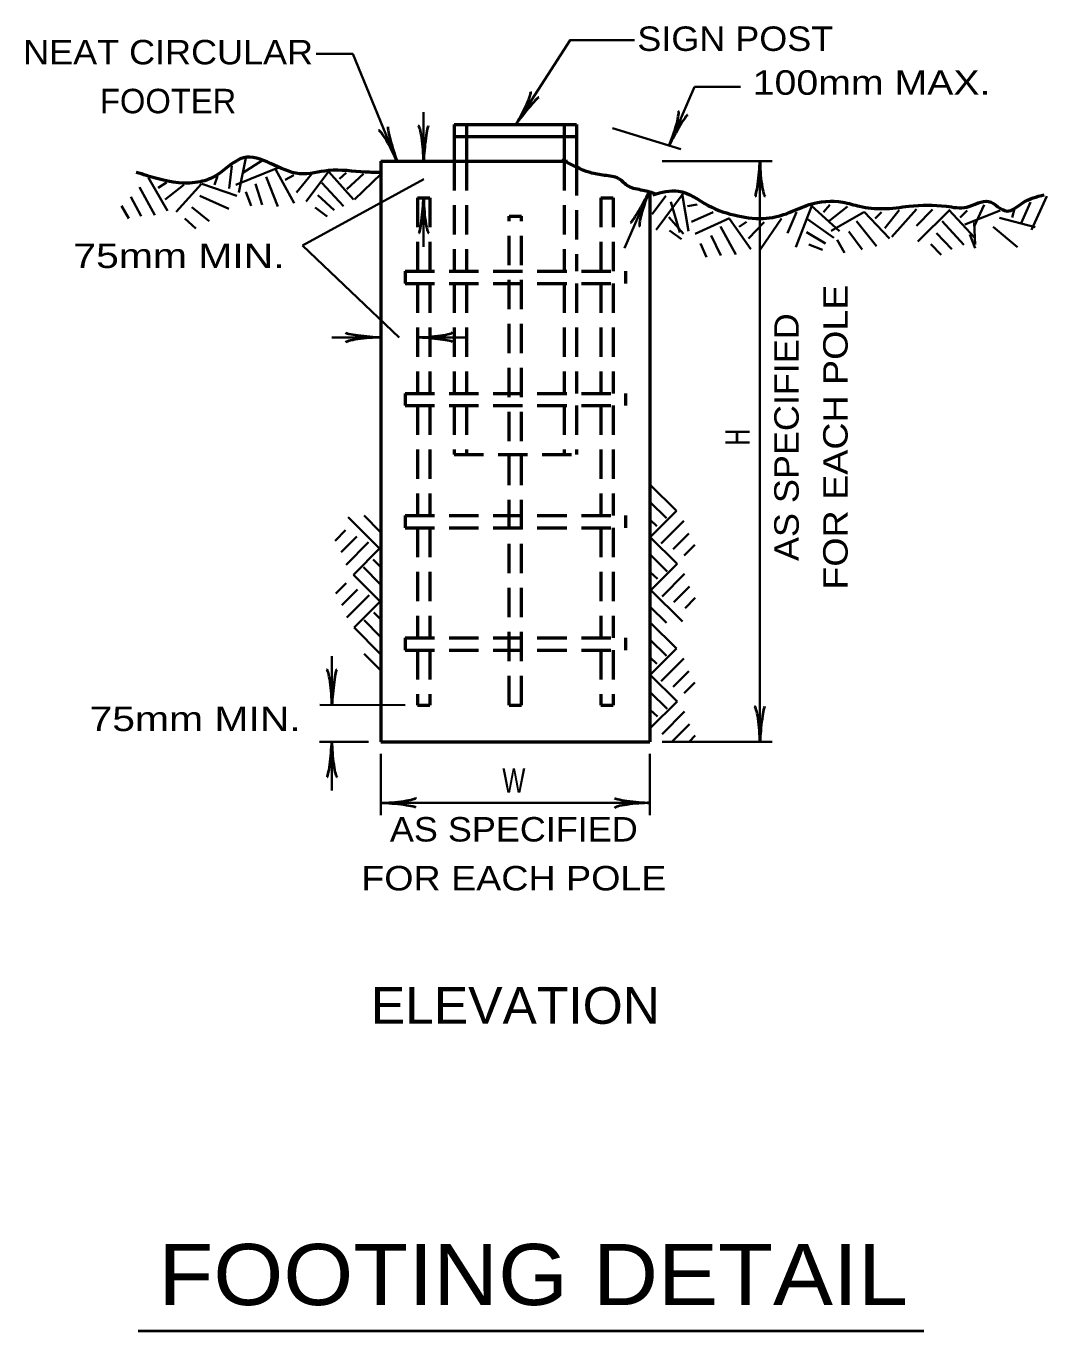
# Model space of a CAD drawing. Extents: x -27 to 828, y -12 to 532.
# Drawn here: x 442.8 to 542.9, y 166.3 to 294.4 of the extents above; entities that cross this region are included whole.
import ezdxf
from ezdxf.enums import TextEntityAlignment as Align

# ---------------------------------------------------------------- set-up
doc = ezdxf.new("R2010")
doc.units = 0
doc.header["$LTSCALE"] = 0.96
doc.linetypes.add('MEDIUM_DASHED', pattern=[4.5, 3, -1.5])
doc.layers.add('1', color=7, linetype='Continuous', lineweight=35)

msp = doc.modelspace()

# ---------------------------------------------------------------- linework, layer by layer
at = {"layer": '1'}
for p, q in [((505.8728, 282.6366), (508.3642, 288.3828)), ((508.3642, 288.3828), (512.887, 288.3828)), ((481.7762, 281.1069), (481.7762, 285.9069)), ((500.3226, 284.3524), (507.0331, 282.2778)), ((462.9633, 280.631), (462.6927, 278.4073)), ((464.373, 281.5802), (463.6367, 278.024)), ((465.9436, 281.1514), (464.0411, 279.9687)), ((505.1762, 281.1069), (515.9762, 281.1069)), ((514.7762, 281.1069), (514.7762, 224.1069)), ((454.778, 279.4722), (456.6378, 276.2349)), ((461.5546, 279.6169), (461.2696, 278.7817)), ((467.4886, 280.4349), (463.3678, 278.7651)), ((466.3373, 279.5709), (467.474, 276.6443)), ((467.2913, 280.2549), (469.0651, 276.9697)), ((469.039, 279.7328), (468.1959, 279.2583)), ((470.7845, 279.828), (469.2964, 278.0196)), ((481.8107, 279.3192), (469.8875, 272.8224)), ((472.4682, 280.1103), (470.2438, 277.1329)), ((472.4657, 280.0413), (474.8968, 277.3433)), ((474.1675, 279.9531), (473.5125, 279.3617)), ((475.8933, 279.8651), (474.2307, 278.3638)), ((477.5996, 279.8586), (475.0005, 277.3221)), ((453.9006, 278.5569), (455.4045, 275.801)), ((456.5465, 279.0168), (455.7448, 278.4752)), ((458.2618, 278.7806), (456.4249, 277.3279)), ((459.9754, 278.8812), (457.4907, 276.1173)), ((460.0252, 278.8655), (463.4624, 277.693)), ((464.344, 278.0826), (464.8505, 276.7319)), ((465.2849, 278.8684), (465.9522, 276.8012)), ((471.7986, 278.9801), (473.9151, 276.6842)), ((501.5022, 272.5563), (503.889, 278.0612)), ((452.1493, 276.7267), (452.8483, 275.4648)), ((453.041, 277.6119), (454.0712, 275.6996)), ((459.8051, 277.6916), (462.6641, 276.4359)), ((471.3892, 277.7657), (472.9887, 276.296)), ((481.7762, 272.7069), (481.7762, 277.5069)), ((505.5501, 277.6915), (504.2154, 275.8925)), ((507.2357, 277.9413), (504.5864, 274.3705)), ((506.0429, 277.1085), (506.9159, 274.0927)), ((507.1495, 277.9097), (507.7565, 274.2258)), ((508.6318, 276.8467), (507.6801, 276.6727)), ((519.9205, 276.8087), (518.3152, 272.6623)), ((519.8294, 276.7304), (522.5968, 274.2243)), ((521.6512, 276.8206), (521.0145, 276.0922)), ((536.7836, 276.8257), (535.7945, 274.7029)), ((541.3435, 277.0668), (540.4192, 275.0262)), ((542.9382, 277.6672), (541.4397, 274.359)), ((458.3395, 275.4617), (459.4204, 274.4811)), ((459.0429, 276.5873), (460.734, 275.2239)), ((471.1485, 276.5568), (472.3137, 275.678)), ((505.8362, 275.5933), (507.2687, 273.9604)), ((510.1984, 276.1041), (508.0549, 275.1608)), ((511.7941, 275.5048), (508.416, 273.9552)), ((511.7944, 275.443), (513.8853, 272.4736)), ((516.8906, 275.4733), (514.8385, 272.477)), ((518.3683, 276.1003), (517.4853, 274.0415)), ((519.4613, 275.4065), (522.0201, 273.5872)), ((523.3626, 276.6413), (521.5219, 275.1934)), ((524.9828, 276.1067), (521.7556, 274.2633)), ((525.0146, 276.1408), (527.5079, 273.5002)), ((526.7192, 276.1009), (526.0934, 275.4787)), ((528.4434, 276.2832), (527.0496, 274.5294)), ((530.1401, 276.4017), (527.7286, 273.6861)), ((531.7232, 276.3471), (530.1397, 274.7626)), ((533.4268, 276.3327), (530.2606, 273.2111)), ((533.3048, 276.3085), (535.8558, 273.5824)), ((535.1278, 276.248), (534.4331, 275.5747)), ((538.3478, 276.2539), (534.8975, 274.8724)), ((538.2868, 275.5487), (541.8019, 274.6359)), ((539.7545, 276.4153), (539.5407, 275.5591)), ((505.9071, 274.2992), (507.0757, 273.4533)), ((510.9113, 274.6717), (512.4221, 271.9389)), ((513.4732, 275.1515), (512.7517, 274.6435)), ((515.2091, 275.1177), (513.6486, 273.5106)), ((519.3394, 274.1185), (521.2135, 273.0201)), ((523.5134, 274.1946), (524.7988, 272.4435)), ((524.2695, 275.2198), (526.204, 272.7686)), ((532.6758, 275.1993), (534.8027, 272.8899)), ((535.7872, 275.0956), (535.9042, 272.9265)), ((537.6555, 274.6643), (540.0602, 272.6724)), ((508.9346, 273.0164), (509.5371, 271.6871)), ((509.9831, 273.7951), (510.9511, 271.8505)), ((519.5657, 272.9315), (520.9106, 272.4096)), ((522.3555, 273.3743), (523.0736, 272.1037)), ((531.5547, 272.9379), (532.5795, 271.9226)), ((532.1211, 274.0486), (533.6186, 272.475)), ((535.3694, 273.9092), (535.9057, 272.5519)), ((479.3873, 263.8044), (469.8875, 272.8224)), ((472.7762, 263.8044), (477.5762, 263.8044)), ((481.1762, 263.8044), (485.9762, 263.8044)), ((504.0242, 249.3309), (506.5922, 246.7629)), ((504.0242, 247.6269), (505.6082, 246.0429)), ((477.5282, 243.0189), (474.3842, 246.1629)), ((477.5282, 244.7229), (475.9442, 246.3069)), ((504.0242, 244.1949), (506.5922, 246.7629)), ((474.1202, 244.8669), (473.1122, 243.8349)), ((504.0242, 245.8989), (504.6482, 245.2749)), ((505.1042, 243.5709), (507.3122, 245.7789)), ((475.2242, 244.2669), (473.6882, 242.7309)), ((476.3762, 243.7149), (474.1682, 241.4829)), ((504.0242, 244.1949), (506.6642, 241.5789)), ((506.2562, 243.0189), (507.7922, 244.5549)), ((507.3602, 242.3949), (508.3922, 243.4269)), ((477.5282, 243.1389), (474.8882, 240.4989)), ((504.0242, 242.4909), (505.6802, 240.8349)), ((477.5282, 239.5869), (475.8722, 241.2429)), ((477.5282, 241.3149), (476.8322, 241.9869)), ((504.0242, 238.9389), (506.6642, 241.5789)), ((474.1922, 239.6829), (473.1602, 238.6509)), ((477.5282, 237.8829), (474.8882, 240.4989)), ((504.0242, 240.7629), (504.7202, 240.0909)), ((505.1762, 238.3629), (507.3842, 240.5949)), ((475.2962, 239.0589), (473.7602, 237.5229)), ((476.4482, 238.5069), (474.2402, 236.2989)), ((504.0242, 239.0589), (507.1682, 235.9149)), ((506.3282, 237.8109), (507.8642, 239.3469)), ((477.5282, 237.8829), (474.9602, 235.3149)), ((504.0242, 237.3549), (505.6082, 235.7709)), ((507.4322, 237.2109), (508.4402, 238.2429)), ((477.5282, 234.4509), (475.9442, 236.0349)), ((477.5282, 236.1789), (476.9042, 236.8029)), ((504.0242, 235.8189), (506.5922, 233.2509)), ((477.5282, 232.7469), (474.9602, 235.3149)), ((504.0242, 234.1149), (505.6082, 232.5309)), ((504.0242, 230.6829), (506.5922, 233.2509)), ((472.7826, 227.7239), (472.7826, 232.5239)), ((477.5282, 231.1629), (475.9442, 232.7469)), ((504.0242, 232.3869), (504.6482, 231.7629)), ((505.1042, 230.0589), (507.3122, 232.2669)), ((504.0242, 230.6829), (506.6642, 228.0669)), ((506.2562, 229.5069), (507.7922, 231.0429)), ((507.3602, 228.8829), (508.3922, 229.9149)), ((504.0242, 228.9789), (505.6802, 227.3229)), ((504.0242, 225.4269), (506.6642, 228.0669)), ((479.9762, 227.709), (471.5826, 227.7239)), ((504.0242, 227.2509), (504.7202, 226.5789)), ((505.1762, 224.8509), (507.3842, 227.0829)), ((506.1362, 224.1069), (507.8642, 225.8349)), ((507.8307, 224.1069), (508.4402, 224.7309)), ((476.3762, 224.1069), (471.5762, 224.1069)), ((472.7762, 224.1069), (472.7762, 219.3069)), ((477.5762, 222.9069), (477.5762, 216.9069)), ((503.9762, 222.9069), (503.9762, 216.9069)), ((505.1762, 224.1069), (515.9762, 224.1069)), ((477.5762, 218.1069), (503.9762, 218.1069))]:
    msp.add_line(p, q, dxfattribs=at)
at = {"layer": '1', "lineweight": 53}
for p, q in [((484.7762, 284.7069), (496.7762, 284.7069)), ((484.7762, 284.7069), (484.7762, 281.1069)), ((485.9762, 284.7069), (485.9762, 281.1069)), ((495.5762, 284.7069), (495.5762, 281.1069)), ((496.7762, 284.7069), (496.7762, 280.6022)), ((484.7762, 283.5069), (496.7762, 283.5069)), ((477.5762, 281.1069), (495.9091, 281.1069)), ((477.5762, 281.1069), (477.5762, 224.1069)), ((503.9762, 278.0362), (503.9762, 224.1069)), ((477.5762, 224.1069), (503.9762, 224.1069))]:
    msp.add_line(p, q, dxfattribs=at)
at = {"layer": '1', "linetype": 'MEDIUM_DASHED', "lineweight": 53}
for p, q in [((484.7762, 281.1069), (484.7762, 270.3069)), ((485.9762, 281.1069), (485.9762, 270.3069)), ((495.5762, 281.1069), (495.5762, 270.3069)), ((496.7762, 280.6022), (496.7762, 270.3069)), ((481.1762, 277.5069), (482.3762, 277.5069)), ((481.1762, 277.5069), (481.1762, 270.3069)), ((482.3762, 277.5069), (482.3762, 270.3069)), ((499.1762, 277.5069), (500.3762, 277.5069)), ((499.1762, 277.5069), (499.1762, 270.3069)), ((500.3762, 277.5069), (500.3762, 270.3069)), ((490.1762, 227.7069), (490.1762, 275.7069)), ((490.1762, 275.7069), (491.3762, 275.7069)), ((491.3762, 227.7069), (491.3762, 275.7069)), ((479.9762, 270.3069), (501.5762, 270.3069)), ((479.9762, 270.3069), (479.9762, 269.1069)), ((501.5762, 270.3069), (501.5762, 269.1069)), ((479.9762, 269.1069), (501.5762, 269.1069)), ((481.1762, 269.1069), (481.1762, 258.3069)), ((482.3762, 269.1069), (482.3762, 258.3069)), ((484.7762, 269.1069), (484.7762, 258.3069)), ((485.9762, 269.1069), (485.9762, 258.3069)), ((495.5762, 269.1069), (495.5762, 258.3069)), ((496.7762, 269.1069), (496.7762, 258.3069)), ((499.1762, 269.1069), (499.1762, 258.3069)), ((500.3762, 269.1069), (500.3762, 258.3069)), ((479.9762, 258.3069), (501.5762, 258.3069)), ((479.9762, 258.3069), (479.9762, 257.1069)), ((501.5762, 258.3069), (501.5762, 257.1069)), ((479.9762, 257.1069), (501.5762, 257.1069)), ((481.1762, 257.1069), (481.1762, 246.3069)), ((482.3762, 257.1069), (482.3762, 246.3069)), ((484.7762, 257.1069), (484.7762, 252.3069)), ((485.9762, 257.1069), (485.9762, 252.3069)), ((495.5762, 257.1069), (495.5762, 252.3069)), ((496.7762, 257.1069), (496.7762, 252.3069)), ((499.1762, 257.1069), (499.1762, 246.3069)), ((500.3762, 257.1069), (500.3762, 246.3069)), ((484.7762, 252.3069), (496.7762, 252.3069)), ((479.9762, 246.3069), (501.5762, 246.3069)), ((479.9762, 246.3069), (479.9762, 245.1069)), ((501.5762, 246.3069), (501.5762, 245.1069)), ((479.9762, 245.1069), (501.5762, 245.1069)), ((481.1762, 245.1069), (481.1762, 234.3069)), ((482.3762, 245.1069), (482.3762, 234.3069)), ((499.1762, 245.1069), (499.1762, 234.3069)), ((500.3762, 245.1069), (500.3762, 234.3069)), ((479.9762, 234.3069), (501.5762, 234.3069)), ((479.9762, 234.3069), (479.9762, 233.1069)), ((501.5762, 234.3069), (501.5762, 233.1069)), ((479.9762, 233.1069), (501.5762, 233.1069)), ((481.1762, 233.1069), (481.1762, 227.7069)), ((482.3762, 233.1069), (482.3762, 227.7069)), ((499.1762, 233.1069), (499.1762, 227.7069)), ((500.3762, 233.1069), (500.3762, 227.7069)), ((481.1762, 227.7069), (482.3762, 227.7069)), ((490.1762, 227.7069), (491.3762, 227.7069)), ((499.1762, 227.7069), (500.3762, 227.7069))]:
    msp.add_line(p, q, dxfattribs=at)
at = {"layer": '1', "lineweight": 40}
msp.add_line((453.784, 166.2729), (530.8554, 166.2729), dxfattribs=at)
at = {"layer": '1'}
for points in [[(490.8331, 284.7069), (496.1572, 292.9917), (502.4581, 292.9917)], [(479.1588, 281.1069), (474.8313, 291.6341), (471.2394, 291.6341)]]:
    msp.add_lwpolyline(points, dxfattribs=at)
at = {"layer": '1', "lineweight": 40}
for centre, major_axis, ratio, start_param, end_param in [((491.2621, 285.9877), (-1.0008, -1.904), 0.122415, 0.89635335, 3.14159265), ((491.2621, 285.9877), (-1.0008, -1.904), 0.122415, 0.89635335, 3.14159265), ((491.7736, 285.7008), (1.3168, 1.6592), 0.07063, 6.28230741, 8.55970261), ((491.7736, 285.7008), (1.3168, 1.6592), 0.07063, 6.28230741, 8.55970261), ((506.0895, 283.9699), (-0.6805, -2.0405), 0.122415, 0.89635335, 3.14159265), ((506.0895, 283.9699), (-0.6805, -2.0405), 0.122415, 0.89635335, 3.14159265), ((506.6406, 283.7692), (-1.0318, -1.85), 0.07063, 3.14071475, 5.41810995), ((506.6406, 283.7692), (-1.0318, -1.85), 0.07063, 3.14071475, 5.41810995), ((478.8824, 282.4471), (-0.6064, 2.0296), 0.07063, 6.28230741, 8.55970261), ((478.8824, 282.4471), (-0.6064, 2.0296), 0.07063, 6.28230741, 8.55970261), ((481.4446, 282.4163), (0.1874, -2.1428), 0.122415, 0.89635335, 3.14159265), ((481.4446, 282.4163), (0.1874, -2.1428), 0.122415, 0.89635335, 3.14159265), ((482.0301, 282.4515), (-0.2108, -2.1077), 0.07063, 3.14071475, 5.41810995), ((482.0301, 282.4515), (-0.2108, -2.1077), 0.07063, 3.14071475, 5.41810995), ((478.3543, 282.1919), (0.988, -1.9107), 0.122415, 0.89635335, 3.14159265), ((478.3543, 282.1919), (0.988, -1.9107), 0.122415, 0.89635335, 3.14159265), ((514.5223, 279.7623), (0.2108, 2.1077), 0.07063, 3.14071475, 5.41810995), ((514.5223, 279.7623), (0.2108, 2.1077), 0.07063, 3.14071475, 5.41810995), ((515.1078, 279.7975), (-0.1874, 2.1428), 0.122415, 0.89635335, 3.14159265), ((515.1078, 279.7975), (-0.1874, 2.1428), 0.122415, 0.89635335, 3.14159265), ((503.1212, 276.9286), (1.0318, 1.8499), 0.07063, 3.14071475, 5.41810995), ((503.6723, 276.7279), (0.6805, 2.0405), 0.122415, 0.89635335, 3.14159265), ((481.5223, 276.1623), (0.2108, 2.1077), 0.07063, 3.14071475, 5.41810995), ((481.5223, 276.1623), (0.2108, 2.1077), 0.07063, 3.14071475, 5.41810995), ((482.1078, 276.1975), (-0.1874, 2.1428), 0.122415, 0.89635335, 3.14159265), ((482.1078, 276.1975), (-0.1874, 2.1428), 0.122415, 0.89635335, 3.14159265), ((476.2316, 264.0583), (2.1077, -0.2108), 0.07063, 3.14071475, 5.41810995), ((476.2316, 264.0583), (2.1077, -0.2108), 0.07063, 3.14071475, 5.41810995), ((482.4856, 264.136), (-2.1428, -0.1874), 0.122415, 0.89635335, 3.14159265), ((476.2668, 263.4728), (2.1428, 0.1874), 0.122415, 0.89635335, 3.14159265), ((476.2668, 263.4728), (2.1428, 0.1874), 0.122415, 0.89635335, 3.14159265), ((482.5208, 263.5505), (-2.1077, 0.2108), 0.07063, 3.14071475, 5.41810995), ((472.451, 229.0333), (0.1874, -2.1428), 0.122415, 0.89635335, 3.14159265), ((472.451, 229.0333), (0.1874, -2.1428), 0.122415, 0.89635335, 3.14159265), ((473.0365, 229.0685), (-0.2108, -2.1077), 0.07063, 3.14071475, 5.41810995), ((473.0365, 229.0685), (-0.2108, -2.1077), 0.07063, 3.14071475, 5.41810995), ((514.4446, 225.4163), (0.1874, -2.1428), 0.122415, 0.89635335, 3.14159265), ((514.4446, 225.4163), (0.1874, -2.1428), 0.122415, 0.89635335, 3.14159265), ((515.0301, 225.4515), (-0.2108, -2.1077), 0.07063, 3.14071475, 5.41810995), ((515.0301, 225.4515), (-0.2108, -2.1077), 0.07063, 3.14071475, 5.41810995), ((472.5223, 222.7623), (0.2108, 2.1077), 0.07063, 3.14071475, 5.41810995), ((472.5223, 222.7623), (0.2108, 2.1077), 0.07063, 3.14071475, 5.41810995), ((473.1078, 222.7975), (-0.1874, 2.1428), 0.122415, 0.89635335, 3.14159265), ((473.1078, 222.7975), (-0.1874, 2.1428), 0.122415, 0.89635335, 3.14159265), ((478.9208, 217.853), (-2.1077, 0.2108), 0.07063, 3.14071475, 5.41810995), ((478.9208, 217.853), (-2.1077, 0.2108), 0.07063, 3.14071475, 5.41810995), ((478.8856, 218.4385), (-2.1428, -0.1874), 0.122415, 0.89635335, 3.14159265), ((478.8856, 218.4385), (-2.1428, -0.1874), 0.122415, 0.89635335, 3.14159265), ((502.6668, 217.7753), (2.1428, 0.1874), 0.122415, 0.89635335, 3.14159265), ((502.6668, 217.7753), (2.1428, 0.1874), 0.122415, 0.89635335, 3.14159265), ((502.6316, 218.3608), (2.1077, -0.2108), 0.07063, 3.14071475, 5.41810995), ((502.6316, 218.3608), (2.1077, -0.2108), 0.07063, 3.14071475, 5.41810995)]:
    msp.add_ellipse(centre, major_axis=major_axis, ratio=ratio, start_param=start_param, end_param=end_param, dxfattribs=at)
at = {"layer": '1', "lineweight": 53}
for points in [[(477.5762, 280.0039), (476.0608, 280.0224), (472.4432, 280.1798), (469.6121, 279.8651), (464.1071, 281.4385), (461.4333, 279.7078), (459.8604, 279.0784), (455.6137, 279.3931), (453.5762, 280.0039)], [(504.6232, 277.8506), (503.285, 278.2345), (501.877, 278.6369), (500.9383, 279.3747), (499.5302, 279.71), (498.1222, 279.9783), (495.3732, 281.2526)], [(504.2669, 277.7978), (506.7861, 278.171), (509.6959, 276.7549), (512.6057, 275.7322), (515.4368, 275.4962), (517.6388, 276.0469), (519.6049, 276.8336), (522.9078, 277.0696), (524.5593, 276.6763), (526.84, 276.4403), (529.4352, 276.6763), (533.0527, 276.6763), (535.0974, 276.5976), (537.2208, 277.1483), (539.0295, 276.2043), (540.5238, 276.9909), (542.6669, 277.7978)]]:
    msp.add_spline(points, degree=3, dxfattribs=at)

# ---------------------------------------------------------------- texts
at = {"layer": '1'}
for s, height, width, p in [('SIGN POST', 2.4, 1.1, (502.7489, 291.925)), ('100mm MAX.', 2.4, 1.2, (514.0722, 287.6203)), ('75mm MIN.', 2.4, 1.25, (447.4095, 270.6104)), ('75mm MIN.', 2.4, 1.25, (448.9946, 225.1571)), ('ELEVATION', 3.6, 1.05, (476.597, 196.4183)), ('FOOTING DETAIL', 6, 1.1, (455.7555, 168.8085))]:
    msp.add_text(s, height=height, dxfattribs=dict(at, width=width)).set_placement(p)
for s, width, p in [('NEAT CIRCULAR', 1.1, (456.7043, 290.6039)), ('W', 0.75, (490.6318, 219.1146)), ('AS SPECIFIED', 1.1, (490.6318, 214.3146)), ('FOR EACH POLE', 1.15, (490.6319, 209.5146))]:
    msp.add_text(s, height=2.4, dxfattribs=dict(at, width=width)).set_placement(p, align=Align.CENTER)
msp.add_text('FOOTER', height=2.4, dxfattribs=at).set_placement((456.7043, 285.8039), align=Align.CENTER)
for s, width, p in [('FOR EACH POLE', 1.15, (523.3862, 254.0108)), ('AS SPECIFIED', 1.1, (518.5862, 254.0106)), ('H', 0.7, (513.7862, 254.0108))]:
    msp.add_text(s, height=2.4, rotation=90, dxfattribs=dict(at, width=width)).set_placement(p, align=Align.CENTER)

doc.saveas('drawing.dxf')
